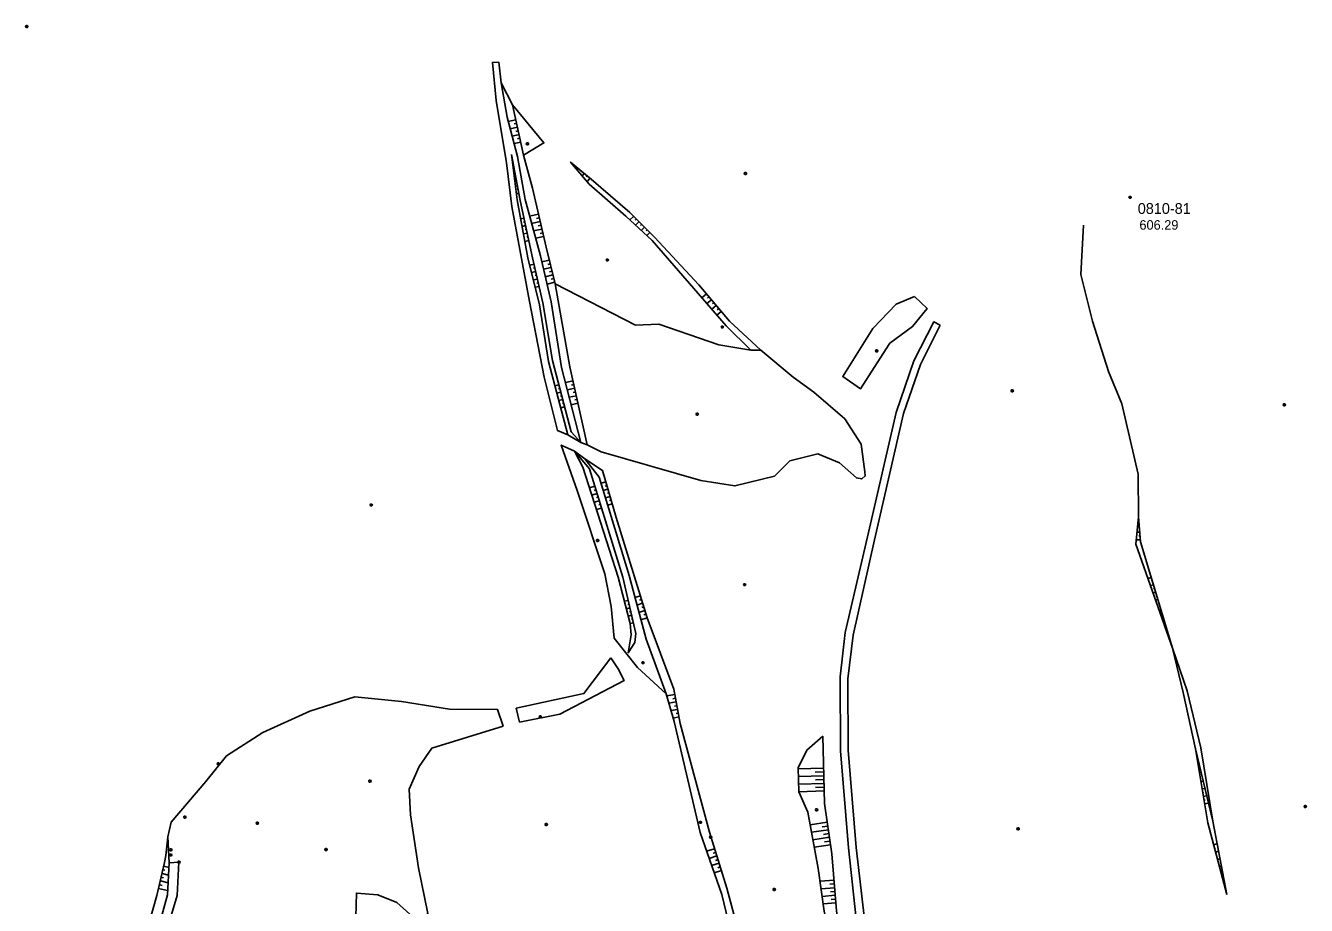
# Model space of a CAD drawing. Extents: x -664960 to -662754, y -993849 to -991145.
# Drawn here: x -663266 to -662862.8, y -992059.4 to -991782.3 of the extents above; entities that cross this region are included whole.
import ezdxf

# ---------------------------------------------------------------- set-up
doc = ezdxf.new("R2010")
doc.units = 0
for name, color, linetype in [('Vrstva 1', 7, 'Continuous'), ('Vrstva 13', 7, 'Continuous'), ('Vrstva 18', 7, 'Continuous'), ('Vrstva 27', 7, 'Continuous'), ('Vrstva 28', 7, 'Continuous'), ('Vrstva 37', 7, 'Continuous'), ('Vrstva 63', 7, 'Continuous'), ('Vrstva 8', 7, 'Continuous')]:
    doc.layers.add(name, color=color, linetype=linetype)

msp = doc.modelspace()

# ---------------------------------------------------------------- linework, layer by layer
at = {"layer": 'Vrstva 13'}
for points in [[(-663265.449, -991782.32), (-663265.269, -991782.62), (-663265.449, -991782.92), (-663265.809, -991782.92), (-663265.989, -991782.62), (-663265.809, -991782.32), (-663265.449, -991782.32)], [(-663107.83, -991819.223), (-663107.65, -991819.523), (-663107.83, -991819.823), (-663108.19, -991819.823), (-663108.37, -991819.523), (-663108.19, -991819.223), (-663107.83, -991819.223)], [(-663039.212, -991828.574), (-663039.032, -991828.874), (-663039.212, -991829.174), (-663039.572, -991829.174), (-663039.752, -991828.874), (-663039.572, -991828.574), (-663039.212, -991828.574)], [(-663082.665, -991855.838), (-663082.485, -991856.138), (-663082.665, -991856.438), (-663083.025, -991856.438), (-663083.205, -991856.138), (-663083.025, -991855.838), (-663082.665, -991855.838)], [(-662997.893, -991884.465), (-662997.713, -991884.765), (-662997.893, -991885.065), (-662998.253, -991885.065), (-662998.433, -991884.765), (-662998.253, -991884.465), (-662997.893, -991884.465)], [(-662955.24, -991897.006), (-662955.06, -991897.306), (-662955.24, -991897.606), (-662955.6, -991897.606), (-662955.78, -991897.306), (-662955.6, -991897.006), (-662955.24, -991897.006)], [(-662869.599, -991901.426), (-662869.419, -991901.726), (-662869.599, -991902.026), (-662869.959, -991902.026), (-662870.139, -991901.726), (-662869.959, -991901.426), (-662869.599, -991901.426)], [(-663054.407, -991904.367), (-663054.227, -991904.667), (-663054.407, -991904.967), (-663054.767, -991904.967), (-663054.947, -991904.667), (-663054.767, -991904.367), (-663054.407, -991904.367)], [(-663157.023, -991932.993), (-663156.843, -991933.293), (-663157.023, -991933.593), (-663157.383, -991933.593), (-663157.563, -991933.293), (-663157.383, -991932.993), (-663157.023, -991932.993)], [(-663085.771, -991944.178), (-663085.591, -991944.478), (-663085.771, -991944.778), (-663086.131, -991944.778), (-663086.311, -991944.478), (-663086.131, -991944.178), (-663085.771, -991944.178)], [(-663039.479, -991958.077), (-663039.299, -991958.377), (-663039.479, -991958.677), (-663039.839, -991958.677), (-663040.019, -991958.377), (-663039.839, -991958.077), (-663039.479, -991958.077)], [(-663071.47, -991982.631), (-663071.29, -991982.931), (-663071.47, -991983.231), (-663071.83, -991983.231), (-663072.01, -991982.931), (-663071.83, -991982.631), (-663071.47, -991982.631)], [(-663103.802, -991999.702), (-663103.622, -992000.002), (-663103.802, -992000.302), (-663104.162, -992000.302), (-663104.342, -992000.002), (-663104.162, -991999.702), (-663103.802, -991999.702)], [(-663157.44, -992019.965), (-663157.26, -992020.265), (-663157.44, -992020.565), (-663157.8, -992020.565), (-663157.98, -992020.265), (-663157.8, -992019.965), (-663157.44, -992019.965)], [(-662862.989, -992027.964), (-662862.809, -992028.264), (-662862.989, -992028.564), (-662863.349, -992028.564), (-662863.529, -992028.264), (-662863.349, -992027.964), (-662862.989, -992027.964)], [(-663016.82, -992028.962), (-663016.64, -992029.262), (-663016.82, -992029.562), (-663017.18, -992029.562), (-663017.36, -992029.262), (-663017.18, -992028.962), (-663016.82, -992028.962)], [(-663192.866, -992033.168), (-663192.686, -992033.468), (-663192.866, -992033.768), (-663193.226, -992033.768), (-663193.406, -992033.468), (-663193.226, -992033.168), (-663192.866, -992033.168)], [(-663101.925, -992033.618), (-663101.745, -992033.918), (-663101.925, -992034.218), (-663102.285, -992034.218), (-663102.465, -992033.918), (-663102.285, -992033.618), (-663101.925, -992033.618)], [(-663053.364, -992032.903), (-663053.184, -992033.203), (-663053.364, -992033.503), (-663053.724, -992033.503), (-663053.904, -992033.203), (-663053.724, -992032.903), (-663053.364, -992032.903)], [(-662953.374, -992034.96), (-662953.194, -992035.26), (-662953.374, -992035.56), (-662953.734, -992035.56), (-662953.914, -992035.26), (-662953.734, -992034.96), (-662953.374, -992034.96)], [(-663030.149, -992054.045), (-663029.969, -992054.345), (-663030.149, -992054.645), (-663030.509, -992054.645), (-663030.689, -992054.345), (-663030.509, -992054.045), (-663030.149, -992054.045)]]:
    msp.add_lwpolyline(points, dxfattribs=at)
at = {"layer": 'Vrstva 18'}
for points in [[(-663205.15, -992014.5), (-663204.97, -992014.8), (-663205.15, -992015.1), (-663205.51, -992015.1), (-663205.69, -992014.8), (-663205.51, -992014.5), (-663205.15, -992014.5)], [(-663215.69, -992031.28), (-663215.51, -992031.58), (-663215.69, -992031.88), (-663216.05, -992031.88), (-663216.23, -992031.58), (-663216.05, -992031.28), (-663215.69, -992031.28)], [(-663220.1, -992041.58), (-663219.92, -992041.88), (-663220.1, -992042.18), (-663220.46, -992042.18), (-663220.64, -992041.88), (-663220.46, -992041.58), (-663220.1, -992041.58)], [(-663220.1, -992043.2), (-663219.92, -992043.5), (-663220.1, -992043.8), (-663220.46, -992043.8), (-663220.64, -992043.5), (-663220.46, -992043.2), (-663220.1, -992043.2)], [(-663217.55, -992045.44), (-663217.37, -992045.74), (-663217.55, -992046.04), (-663217.91, -992046.04), (-663218.09, -992045.74), (-663217.91, -992045.44), (-663217.55, -992045.44)]]:
    msp.add_lwpolyline(points, dxfattribs=at)
at = {"layer": 'Vrstva 27'}
msp.add_line((-663220.75, -992045.93), (-663217.73, -992045.74), dxfattribs=at)
for points in [[(-663004.49, -992063.62), (-663006.99, -992041.22), (-663009.42, -992010.75), (-663009.6, -991987.42), (-663007.99, -991973.44), (-663000.95, -991943.27), (-662991.9, -991904.11), (-662986.4, -991887.86), (-662980.12, -991875.63), (-662978.06, -991876.61)], [(-662978.06, -991876.61), (-662984.27, -991889.03), (-662989.64, -991904.5), (-662998.75, -991944.26), (-663005.51, -991974.26), (-663007.17, -991987.98), (-663007.08, -992010.47), (-663004.54, -992041.19), (-663001.94, -992063.69)], [(-663255.19, -992199.64), (-663251.78, -992197.15), (-663247.85, -992190.65), (-663245.73, -992186.53), (-663243.33, -992177.92), (-663241.8, -992166.41), (-663241.44, -992149.04), (-663240.1, -992130.6), (-663238.94, -992123.73), (-663233.46, -992107.04), (-663226.63, -992084.4), (-663218.27, -992056.26), (-663217.73, -992045.74)]]:
    msp.add_lwpolyline(points, dxfattribs=at)
at = {"layer": 'Vrstva 28'}
msp.add_lwpolyline([(-663171.24, -992041.49), (-663171.06, -992041.79), (-663171.24, -992042.09), (-663171.6, -992042.09), (-663171.78, -992041.79), (-663171.6, -992041.49), (-663171.24, -992041.49)], dxfattribs=at)
at = {"layer": 'Vrstva 37'}
msp.add_lwpolyline([(-663050.13, -992037.62), (-663049.95, -992037.92), (-663050.13, -992038.22), (-663050.49, -992038.22), (-663050.67, -992037.92), (-663050.49, -992037.62), (-663050.13, -992037.62)], dxfattribs=at)
at = {"layer": 'Vrstva 63'}
for p, q in [((-663111.689, -991811.956), (-663114.066, -991812.483)), ((-663111.169, -991814.299), (-663113.447, -991814.804)), ((-663111.429, -991813.127), (-663112.204, -991813.299)), ((-663110.65, -991816.642), (-663112.829, -991817.125)), ((-663110.909, -991815.47), (-663111.652, -991815.635)), ((-663110.39, -991817.813), (-663111.099, -991817.971)), ((-663110.13, -991818.985), (-663112.21, -991819.447)), ((-663093.878, -991825.782), (-663093.964, -991825.887)), ((-663092.954, -991826.548), (-663093.028, -991826.638)), ((-663112.096, -991828.049), (-663112.387, -991828.104)), ((-663111.655, -991830.408), (-663112.08, -991830.488)), ((-663111.875, -991829.229), (-663111.995, -991829.251)), ((-663092.03, -991827.314), (-663092.392, -991827.751)), ((-663091.106, -991828.079), (-663091.272, -991828.28)), ((-663090.181, -991828.845), (-663090.819, -991829.614)), ((-663089.257, -991829.61), (-663089.516, -991829.922)), ((-663088.333, -991830.376), (-663089.246, -991831.478)), ((-663111.214, -991832.768), (-663111.772, -991832.872)), ((-663111.434, -991831.588), (-663111.598, -991831.619)), ((-663110.993, -991833.947), (-663111.202, -991833.986)), ((-663110.773, -991835.127), (-663111.465, -991835.256)), ((-663104.552, -991841.7), (-663107.319, -991842.347)), ((-663104.279, -991842.869), (-663105.186, -991843.081)), ((-663074.618, -991842.395), (-663075.744, -991843.528)), ((-663109.126, -991842.975), (-663110.121, -991843.193)), ((-663108.612, -991845.319), (-663109.689, -991845.555)), ((-663108.869, -991844.147), (-663109.214, -991844.222)), ((-663108.355, -991846.491), (-663108.727, -991846.573)), ((-663104.005, -991844.037), (-663106.688, -991844.665)), ((-663103.459, -991846.374), (-663106.058, -991846.982)), ((-663103.732, -991845.206), (-663104.611, -991845.411)), ((-663073.766, -991843.241), (-663074.132, -991843.608)), ((-663072.915, -991844.086), (-663073.983, -991845.161)), ((-663072.064, -991844.932), (-663072.41, -991845.28)), ((-663071.213, -991845.778), (-663072.222, -991846.793)), ((-663070.361, -991846.624), (-663070.688, -991846.952)), ((-663108.098, -991847.663), (-663109.257, -991847.917)), ((-663107.584, -991850.008), (-663108.826, -991850.28)), ((-663107.841, -991848.835), (-663108.241, -991848.923)), ((-663102.912, -991848.711), (-663105.427, -991849.299)), ((-663103.185, -991847.542), (-663104.037, -991847.742)), ((-663069.51, -991847.469), (-663070.46, -991848.426)), ((-663105.94, -991857.435), (-663107.301, -991857.743)), ((-663105.675, -991858.605), (-663106.119, -991858.706)), ((-663101.129, -991856.143), (-663103.481, -991856.719)), ((-663100.558, -991858.474), (-663102.935, -991859.056)), ((-663100.844, -991857.308), (-663101.631, -991857.501)), ((-663105.409, -991859.775), (-663106.716, -991860.072)), ((-663104.878, -991862.116), (-663106.131, -991862.4)), ((-663105.144, -991860.945), (-663105.57, -991861.042)), ((-663099.987, -991860.805), (-663102.388, -991861.393)), ((-663100.273, -991859.639), (-663101.068, -991859.834)), ((-663099.702, -991861.97), (-663100.505, -991862.167)), ((-663104.347, -991864.456), (-663105.545, -991864.728)), ((-663104.612, -991863.286), (-663105.02, -991863.378)), ((-663099.416, -991863.136), (-663101.842, -991863.73)), ((-663051.667, -991866.81), (-663053.072, -991867.998)), ((-663050.117, -991868.642), (-663051.51, -991869.821)), ((-663050.892, -991867.726), (-663051.358, -991868.12)), ((-663048.567, -991870.475), (-663049.949, -991871.643)), ((-663049.342, -991869.559), (-663049.804, -991869.949)), ((-663047.018, -991872.308), (-663048.387, -991873.466)), ((-663047.792, -991871.391), (-663048.251, -991871.779)), ((-663093.653, -991894.185), (-663096.033, -991894.71)), ((-663093.395, -991895.357), (-663094.174, -991895.529)), ((-663098.117, -991895.391), (-663099.371, -991895.718)), ((-663097.512, -991897.714), (-663098.753, -991898.037)), ((-663097.814, -991896.552), (-663098.23, -991896.661)), ((-663097.209, -991898.875), (-663097.62, -991898.982)), ((-663093.136, -991896.528), (-663095.438, -991897.036)), ((-663092.619, -991898.872), (-663094.842, -991899.363)), ((-663092.877, -991897.7), (-663093.631, -991897.866)), ((-663096.907, -991900.036), (-663098.135, -991900.356)), ((-663096.301, -991902.359), (-663097.517, -991902.675)), ((-663096.604, -991901.197), (-663097.011, -991901.303)), ((-663092.101, -991901.216), (-663094.246, -991901.689)), ((-663092.36, -991900.044), (-663093.087, -991900.204)), ((-663093.24, -991916.28), (-663093.24, -991916.28)), ((-663093.24, -991916.28), (-663089.95, -991918.77)), ((-663086.809, -991927.359), (-663088.454, -991927.865)), ((-663083.347, -991926.011), (-663084.827, -991926.441)), ((-663083.012, -991927.163), (-663083.501, -991927.305)), ((-663086.103, -991929.652), (-663087.726, -991930.152)), ((-663086.456, -991928.505), (-663087, -991928.673)), ((-663085.75, -991930.799), (-663086.286, -991930.964)), ((-663082.678, -991928.316), (-663084.131, -991928.738)), ((-663082.008, -991930.62), (-663083.434, -991931.035)), ((-663082.343, -991929.468), (-663082.822, -991929.607)), ((-663085.396, -991931.946), (-663086.997, -991932.439)), ((-663084.69, -991934.239), (-663086.268, -991934.726)), ((-663085.043, -991933.093), (-663085.572, -991933.256)), ((-663081.339, -991932.925), (-663082.738, -991933.331)), ((-663081.673, -991931.773), (-663082.144, -991931.909)), ((-662915.436, -991939.423), (-662915.855, -991939.455)), ((-662915.62, -991937.03), (-662915.62, -991937.03)), ((-662915.528, -991938.226), (-662915.598, -991938.232)), ((-662915.252, -991941.816), (-662916.089, -991941.88)), ((-662915.344, -991940.619), (-662915.553, -991940.635)), ((-662915.16, -991943.012), (-662915.509, -991943.039)), ((-662915.068, -991944.209), (-662916.324, -991944.305)), ((-662911.638, -991956.103), (-662912.66, -991956.41)), ((-662910.948, -991958.402), (-662911.865, -991958.677)), ((-662911.293, -991957.252), (-662911.616, -991957.349)), ((-662910.603, -991959.551), (-662910.89, -991959.637)), ((-663076.308, -991963.345), (-663077.483, -991963.613)), ((-663072.471, -991961.939), (-663074.169, -991962.463)), ((-663072.117, -991963.086), (-663072.698, -991963.265)), ((-662910.258, -991960.7), (-662911.069, -991960.944)), ((-662909.567, -991962.999), (-662910.274, -991963.211)), ((-662909.913, -991961.85), (-662910.165, -991961.926)), ((-663075.773, -991965.684), (-663076.872, -991965.936)), ((-663076.041, -991964.514), (-663076.419, -991964.601)), ((-663075.506, -991966.854), (-663075.859, -991966.935)), ((-663071.764, -991964.233), (-663073.553, -991964.784)), ((-663071.057, -991966.526), (-663072.936, -991967.106)), ((-663071.41, -991965.38), (-663072.021, -991965.568)), ((-663070.703, -991967.673), (-663071.344, -991967.871)), ((-663075.238, -991968.024), (-663076.261, -991968.258)), ((-663074.703, -991970.363), (-663075.65, -991970.58)), ((-663074.971, -991969.194), (-663075.299, -991969.269)), ((-663070.35, -991968.82), (-663072.32, -991969.427)), ((-663061.638, -991992.949), (-663064.17, -991993.41)), ((-663061.208, -991995.311), (-663063.509, -991995.729)), ((-663061.423, -991994.13), (-663062.228, -991994.276)), ((-663060.779, -991997.672), (-663062.847, -991998.048)), ((-663060.35, -992000.033), (-663062.186, -992000.367)), ((-663060.994, -991996.491), (-663061.721, -991996.624)), ((-663060.565, -991998.853), (-663061.215, -991998.971)), ((-663014.796, -992016.146), (-663022.783, -992016.372)), ((-663014.728, -992018.545), (-663022.722, -992018.772)), ((-663014.762, -992017.346), (-663017.422, -992017.421)), ((-663014.694, -992019.745), (-663017.357, -992019.82)), ((-662896.032, -992020.324), (-662895.314, -992020.206)), ((-663014.66, -992020.944), (-663022.661, -992021.171)), ((-663014.592, -992023.343), (-663022.6, -992023.57)), ((-663014.626, -992022.144), (-663017.291, -992022.219)), ((-662895.837, -992021.509), (-662895.57, -992021.465)), ((-662895.642, -992022.693), (-662894.758, -992022.547)), ((-662895.448, -992023.877), (-662895.125, -992023.824)), ((-662895.253, -992025.061), (-662894.202, -992024.888)), ((-662895.058, -992026.245), (-662894.68, -992026.183)), ((-662894.864, -992027.429), (-662893.645, -992027.229)), ((-663013.624, -992033.184), (-663019.02, -992033.968)), ((-663013.279, -992035.559), (-663018.583, -992036.33)), ((-663013.452, -992034.372), (-663015.233, -992034.631)), ((-663012.934, -992037.934), (-663018.146, -992038.691)), ((-663012.59, -992040.31), (-663017.709, -992041.053)), ((-663013.107, -992036.747), (-663014.858, -992037.001)), ((-663012.762, -992039.122), (-663014.482, -992039.372)), ((-662892.061, -992040.268), (-662890.951, -992039.973)), ((-663049.087, -992041.518), (-663051.62, -992042.3)), ((-663048.38, -992043.812), (-663050.833, -992044.568)), ((-663048.734, -992042.665), (-663049.564, -992042.921)), ((-662891.754, -992041.428), (-662891.411, -992041.337)), ((-662891.446, -992042.588), (-662890.5, -992042.337)), ((-662891.139, -992043.748), (-662890.851, -992043.671)), ((-663222.754, -992048.18), (-663222.14, -992048.323)), ((-663222.483, -992047.011), (-663220.838, -992047.393)), ((-663047.673, -992046.105), (-663050.046, -992046.837)), ((-663046.965, -992048.399), (-663049.258, -992049.106)), ((-663048.026, -992044.959), (-663048.83, -992045.206)), ((-663047.319, -992047.252), (-663048.096, -992047.492)), ((-662890.831, -992044.908), (-662890.049, -992044.7)), ((-662890.523, -992046.067), (-662890.29, -992046.006)), ((-662890.216, -992047.227), (-662889.598, -992047.063)), ((-663223.568, -992051.687), (-663221.131, -992052.253)), ((-663223.297, -992050.518), (-663222.551, -992050.691)), ((-663223.025, -992049.349), (-663220.984, -992049.823)), ((-663011.513, -992051.405), (-663015.907, -992051.759)), ((-663011.417, -992052.601), (-663012.856, -992052.717)), ((-663224.111, -992054.025), (-663221.277, -992054.683)), ((-663223.84, -992052.856), (-663222.962, -992053.059)), ((-663011.32, -992053.797), (-663015.573, -992054.14)), ((-663011.127, -992056.19), (-663015.239, -992056.521)), ((-663011.224, -992054.994), (-663012.617, -992055.106)), ((-663010.935, -992058.582), (-663014.905, -992058.902)), ((-663011.031, -992057.386), (-663012.377, -992057.494))]:
    msp.add_line(p, q, dxfattribs=at)
for points in [[(-663095.25, -991911.18), (-663098.55, -991909.85), (-663102.79, -991893.06), (-663107.41, -991869.16), (-663112.91, -991839.26), (-663114.56, -991825.5), (-663117.9, -991805.93), (-663119.06, -991793.94), (-663117.07, -991793.81), (-663116.26, -991800.33)], [(-663116.26, -991800.33), (-663112.74, -991807.22), (-663109.21, -991823.13), (-663106.47, -991833.5), (-663102.11, -991852.14), (-663099.29, -991863.65), (-663094.63, -991889.76), (-663089.2, -991914.36), (-663091.19, -991913.62)], [(-663091.19, -991913.62), (-663097.25, -991889.96), (-663100.55, -991869.26), (-663103.92, -991854.84), (-663108.76, -991837.05), (-663111.12, -991823.54), (-663114.41, -991811.19), (-663116.26, -991800.33)], [(-663112.74, -991807.22), (-663102.81, -991819.27), (-663109.21, -991823.13)], [(-663113.06, -991822.89), (-663110.35, -991837.39), (-663106.4, -991855.41), (-663103.17, -991869.64), (-663100.1, -991887.78), (-663094.24, -991910.27), (-663091.19, -991913.62), (-663095.25, -991911.18)], [(-663095.25, -991911.18), (-663101.41, -991888.07), (-663104.17, -991870.2), (-663107.89, -991855.4), (-663111.21, -991837.23), (-663113.06, -991822.89)], [(-663034.55, -991884.49), (-663044.42, -991875.38), (-663054.11, -991863.92), (-663068.02, -991848.95), (-663075.83, -991841.19), (-663087.93, -991830.71), (-663094.46, -991825.3), (-663088.62, -991832.22), (-663077.08, -991842.29), (-663068.73, -991850.03), (-663055.59, -991865.06), (-663045.47, -991876.87), (-663037.66, -991884.54)], [(-662915.62, -991937.03), (-662915.79, -991923.6), (-662920.91, -991901.46), (-662925.08, -991891.29), (-662930.19, -991875.38), (-662933.78, -991860.65), (-662933.01, -991845.15)], [(-663089.2, -991914.36), (-663084.85, -991916.54), (-663053.48, -991925.52), (-663042.69, -991927.26), (-663030.25, -991924.19), (-663025.4, -991919.34), (-663016.6, -991917.12), (-663009.81, -991919.96), (-663004.45, -991924.73), (-663002.76, -991925.06), (-663001.7, -991924.12), (-663001.77, -991922.82), (-663002.94, -991914.12), (-663008.12, -991906.16), (-663017.9, -991897.79), (-663024.36, -991893.08), (-663034.55, -991884.49), (-663037.66, -991884.54), (-663047.72, -991882.83), (-663066.64, -991876.38), (-663074.04, -991876.69), (-663099.29, -991863.65)], [(-662986.13, -991867.62), (-662991.92, -991870.04), (-662999.33, -991877.67), (-663008.77, -991892.83), (-663003.2, -991896.74), (-662998.86, -991890.02), (-662993.91, -991882.33), (-662986.8, -991877.1), (-662982.21, -991871.44), (-662986.13, -991867.62)], [(-663046.49, -991876.94), (-663046.31, -991877.24), (-663046.49, -991877.54), (-663046.85, -991877.54), (-663047.03, -991877.24), (-663046.85, -991876.94), (-663046.49, -991876.94)], [(-663080.73, -991975.2), (-663081.62, -991965.25), (-663083.66, -991954.98), (-663092.38, -991928.75), (-663097.35, -991914.41), (-663093.24, -991916.28)], [(-663093.24, -991916.28), (-663090.54, -991921.32), (-663079.47, -991956.06), (-663075.65, -991970.58), (-663075.35, -991974.17), (-663076.3, -991979.79), (-663074.21, -991976.55), (-663073.94, -991973.7), (-663077.99, -991955.99), (-663088.5, -991921.87), (-663093.24, -991916.28)], [(-663025.19, -992120.68), (-663031.49, -992100.68), (-663038.12, -992078.65), (-663042.66, -992063.66), (-663045.25, -992053.96), (-663050.7, -992036.29), (-663059.98, -992002.07), (-663061.95, -991991.23), (-663070.35, -991968.82), (-663080.1, -991937.19), (-663084.39, -991922.42), (-663089.95, -991918.77)], [(-663089.95, -991918.77), (-663085.41, -991924.52), (-663076.03, -991955.45), (-663070.69, -991975.57), (-663064.35, -991992.78), (-663061.86, -992001.51), (-663053.66, -992036.42), (-663046.87, -992055.99), (-663044.75, -992064.62), (-663040.7, -992080.12), (-663033.54, -992101.23), (-663026.45, -992121.68)], [(-662904.94, -991978.41), (-662916.45, -991945.61), (-662915.62, -991937.03), (-662915.02, -991944.84), (-662904.94, -991978.41)], [(-663080.73, -991975.2), (-663073.42, -991984.45), (-663064.35, -991992.78)], [(-662892.31, -992032.85), (-662896.01, -992009.72), (-662900.32, -991991.8), (-662904.94, -991978.41), (-662901.56, -991992.37), (-662897.71, -992010.12)], [(-663110.51, -992001.65), (-663111.53, -991997.29), (-663090.23, -991992.67), (-663081.76, -991981.41)], [(-663110.51, -992001.65), (-663097.8, -991999.15), (-663077.54, -991988.55), (-663079.47, -991984.88), (-663081.76, -991981.41)], [(-663221.18, -992037.8), (-663220.13, -992033.2), (-663209.26, -992020.37), (-663202.73, -992012.26), (-663191.3, -992004.95), (-663176.56, -991998.25), (-663162.36, -991993.72), (-663147.69, -991995.14), (-663132.56, -991997.61), (-663117.43, -991997.71), (-663115.65, -992002.94)], [(-663135.5, -992177.39), (-663146.12, -992172.92), (-663148.32, -992161.18), (-663153.95, -992156.98), (-663151.59, -992136.77), (-663152.6, -992124.17), (-663150.97, -992116.21), (-663155.04, -992089.45), (-663158.13, -992080.36), (-663159.72, -992069.81), (-663162.02, -992063.04), (-663161.85, -992055.48), (-663155.08, -992056), (-663149.1, -992058.44), (-663145.07, -992062.16), (-663142.16, -992065.15), (-663139.33, -992061.92), (-663142.33, -992047.53), (-663144.85, -992030.82), (-663145.27, -992022.76), (-663142.06, -992015.64), (-663138.15, -992009.85), (-663115.65, -992002.94)], [(-663015.08, -992006.1), (-663020.1, -992010.46), (-663022.79, -992016.08), (-663022.6, -992023.57), (-663019.76, -992029.97), (-663016.47, -992047.75), (-663014.58, -992061.22), (-663008.46, -992089.28), (-663004.47, -992105.85), (-663001.1, -992110.39), (-663002.78, -992103.88), (-663006.23, -992088.8), (-663010.73, -992061.12), (-663012.18, -992043.13), (-663014.48, -992027.29), (-663015.08, -992006.1)], [(-662887.9, -992055.96), (-662892.31, -992032.85), (-662897.71, -992010.12), (-662893.88, -992033.41), (-662887.9, -992055.96)], [(-663249.98, -992189.6), (-663247.97, -992184.61), (-663245.71, -992177.54), (-663244.28, -992166.49), (-663243.73, -992148.95), (-663242.37, -992130.61), (-663241.07, -992123.52), (-663235.94, -992106.39), (-663229.32, -992084.97), (-663221.36, -992056.06), (-663220.75, -992045.93), (-663221.18, -992037.8), (-663221.83, -992043.64), (-663222.22, -992045.88), (-663224.63, -992056.26), (-663232.61, -992084.48), (-663239.28, -992106.13), (-663244.17, -992123.72), (-663245.57, -992130.23), (-663246.51, -992148.72), (-663245.89, -992166.61), (-663246.94, -992178.02), (-663248.85, -992184.55), (-663249.98, -992189.6)]]:
    msp.add_lwpolyline(points, dxfattribs=at)
at = {"layer": 'Vrstva 8'}
msp.add_lwpolyline([(-662918.11, -991836.11), (-662917.93, -991836.41), (-662918.11, -991836.71), (-662918.47, -991836.71), (-662918.65, -991836.41), (-662918.47, -991836.11), (-662918.11, -991836.11)], dxfattribs=at)

# ---------------------------------------------------------------- texts
at = {"layer": 'Vrstva 1'}
msp.add_text('0810-81', height=3.4, dxfattribs=at).set_placement((-662915.89, -991841.61))
at = {"layer": 'Vrstva 63'}
msp.add_text('606.29', height=3, dxfattribs=at).set_placement((-662915.366, -991846.59))

doc.saveas('drawing.dxf')
